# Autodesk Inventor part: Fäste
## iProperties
Author: Tobben
Shininess: 64.0
Angle Display Precision: 2
Document Length Units: 11269
Document Angle Units: 11283
Document Time Units: 11279
Document Mass Units: 11290
Document Length Units Precision: 3
Document Angle Units Precision: 2
Compacted: True
PropertySet Name: _Private Model Information
Created: 2001-12
Part Number: Fäste
Material: S235JRG2
Document SubType Name: Modeling
Designer: Tobben
Control State: 0
Master: False
Checked Out: False
PropertySet Name: Design Tracking Control
Density: 0.0
Volumn: 0.0
Area: 0.0
PropertySet Name: Model Information
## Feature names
1. Extrusion1
2. Extrusion2
3. Extrusion3
4. Extrusion4
5. Hole1
6. Hole2
